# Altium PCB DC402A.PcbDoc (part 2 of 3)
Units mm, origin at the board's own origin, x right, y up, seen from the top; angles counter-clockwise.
Board outline 93 x 73 mm, 4 copper layers (Top Layer, Int1 (GND), Int2 (PWR), Bottom Layer), stack 1.369 mm thick; 244 components, 141 nets, 575 pads, 306 vias.
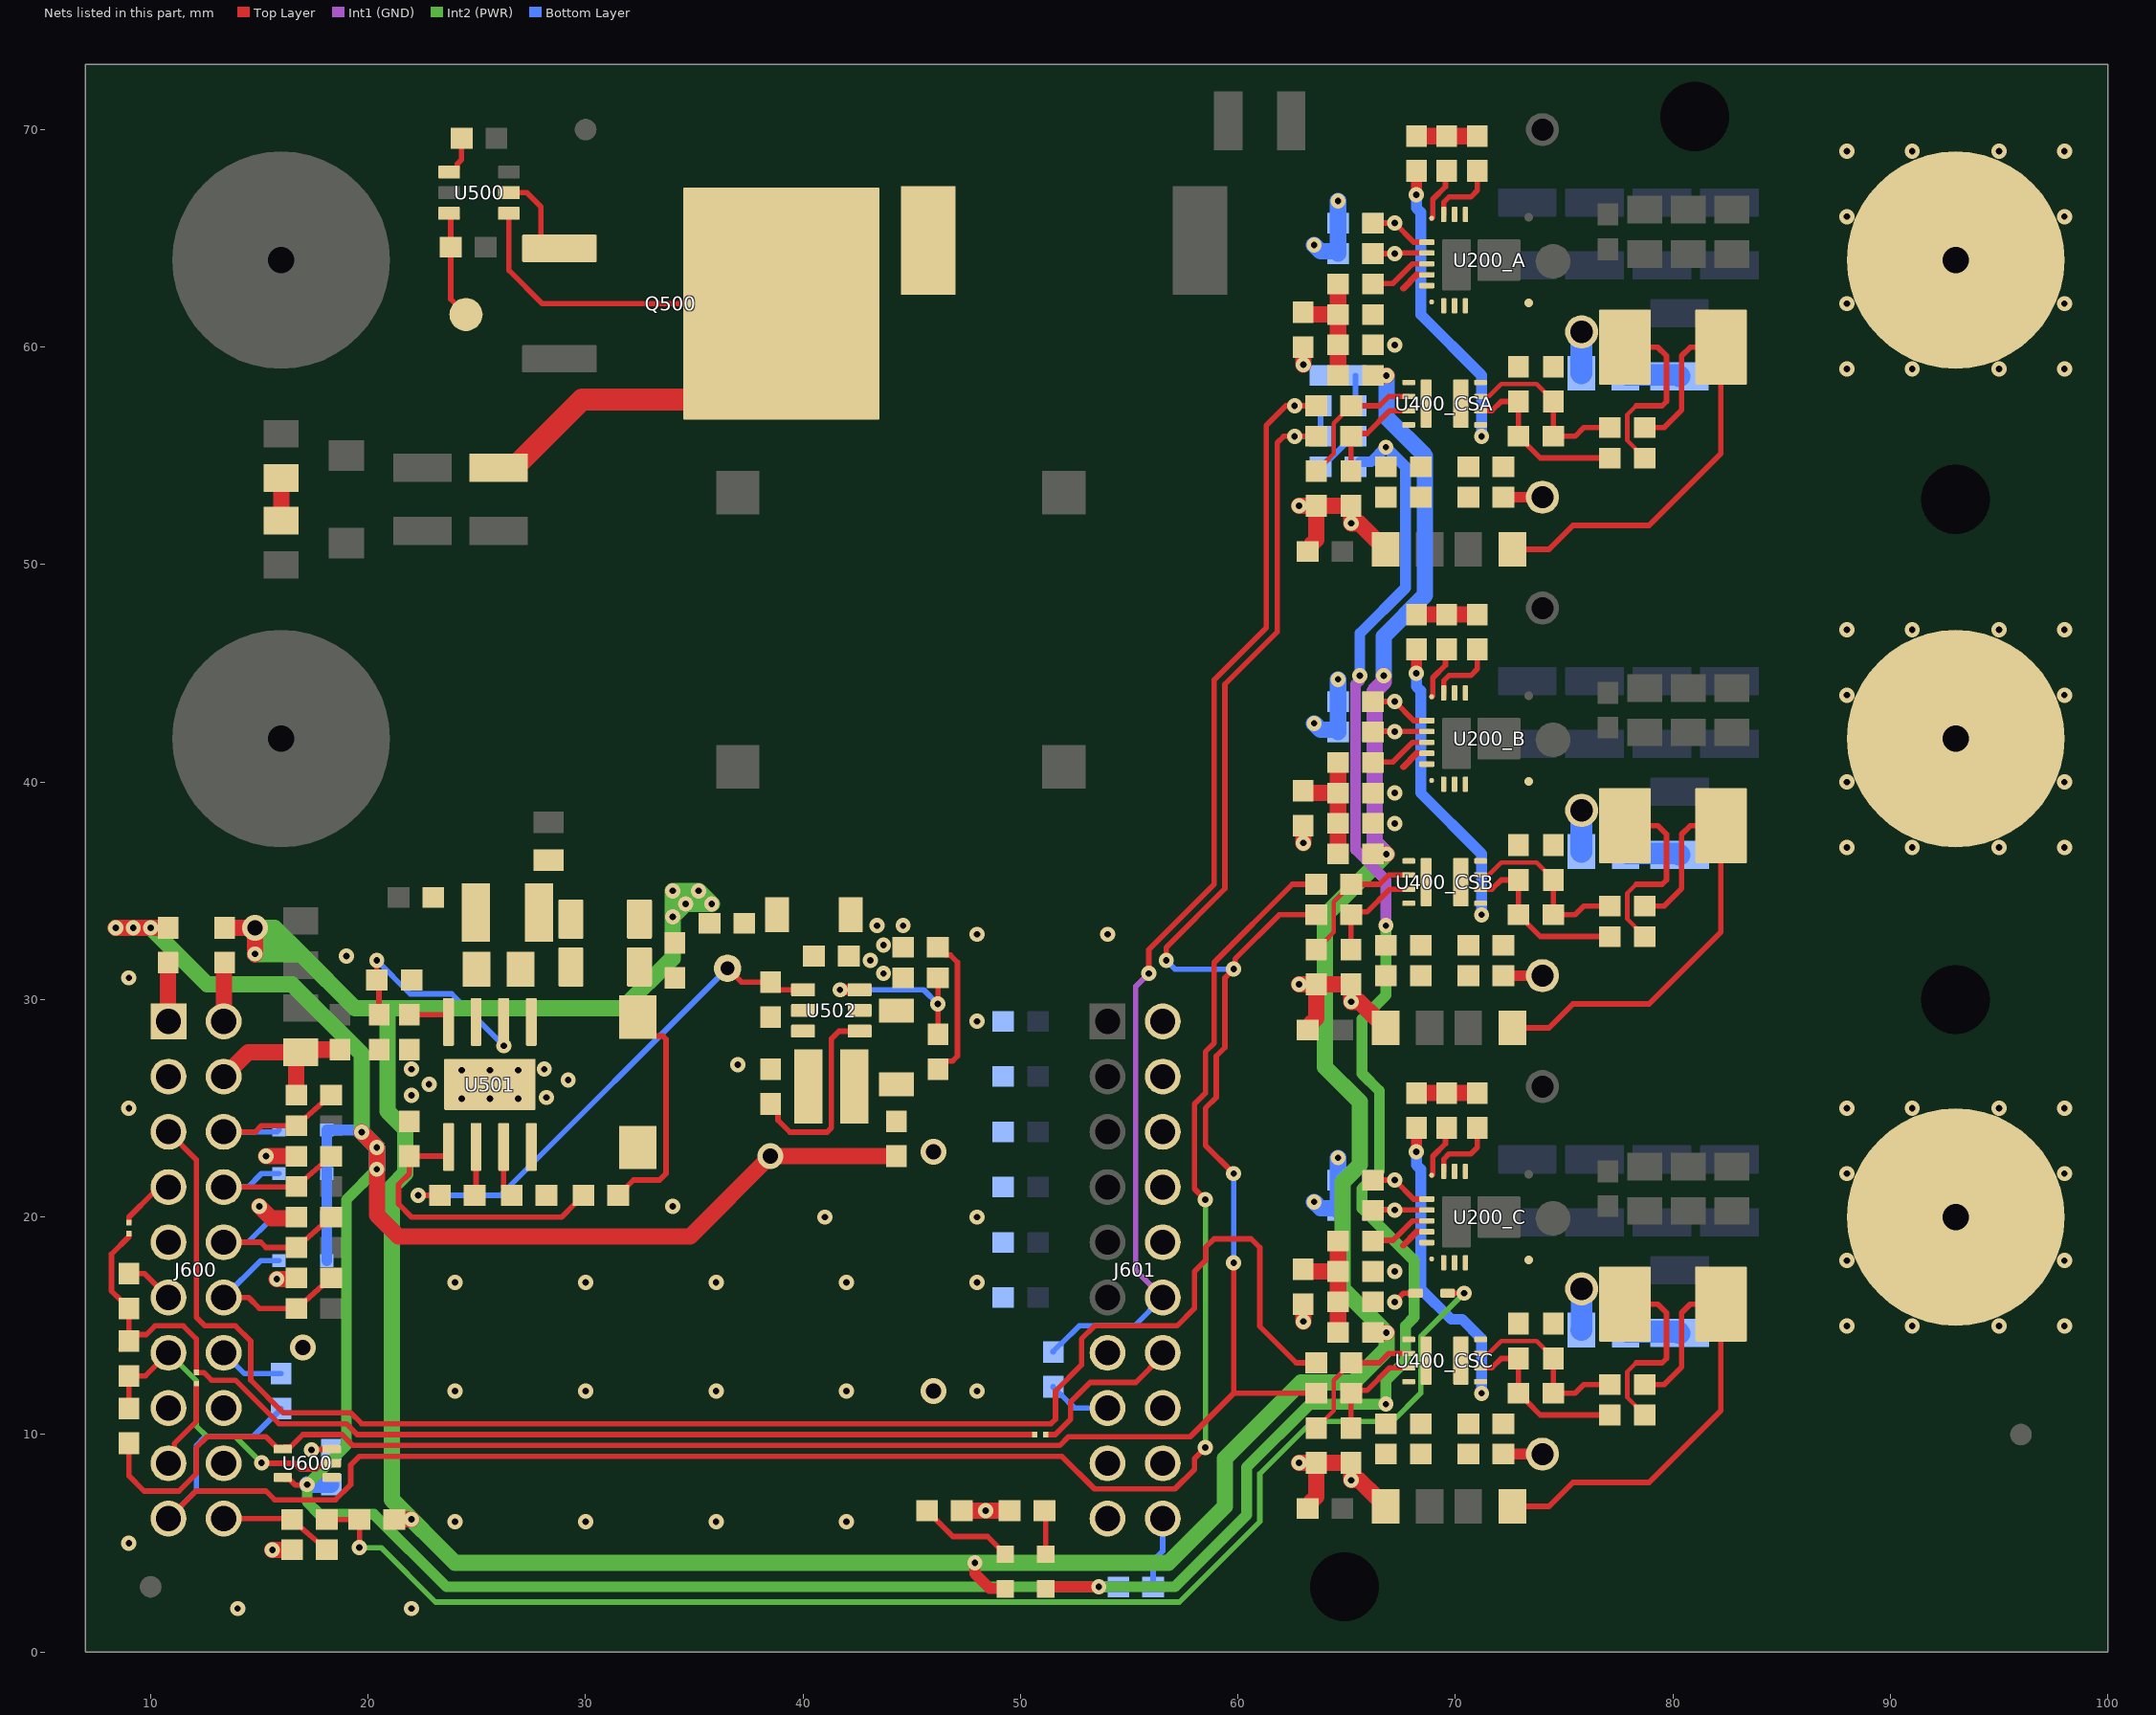
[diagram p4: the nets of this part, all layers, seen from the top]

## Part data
C1 C2: library part CMP-0007197-4, "CAP, CERM, 220 pF, 50 V, +/- 5%, C0G/NP0, 0603", Cap_Case=0603, Manufacturer=MuRata, Supplier Part Number 1=490-1435-1-ND, TempCo=C0G/NP0, Tolerance_%=5%, Value1=Unknown, Value2=50V, ValueDisplayed=220pF
C200_A C200_B C200_C: library part CMP-0007238-4, "CAP, CERM, 1000 pF, 100 V, +/- 5%, C0G/NP0, 0603", Cap_Case=0603, Manufacturer=MuRata, Supplier Part Number 1=490-3281-1-ND, TempCo=C0G/NP0, Tolerance_%=5%, Value1=Unknown, Value2=100V, ValueDisplayed=1000pF
C201_A C201_B C201_C C202_A C202_B C202_C C203_A C203_B C203_C C500 C507 C510: library part CMP-0008249-2, "CAP, CERM, 0.22 uF, 100 V, +/- 10%, X7R, 0805", Cap_Case=0805, Manufacturer=MuRata, Supplier Part Number 1=GRM21AR72A224KAC5-ND, TempCo=X7R, Tolerance_%=10%, Value1=Unknown, Value2=100V, ValueDisplayed=0.22uF
C204_A C204_B C204_C C210_A C210_B C210_C C401_CSA C401_CSB C401_CSC C405_CSA C405_CSB C405_CSC C508 C513 C514 C515 C605: library part CMP-0006837-4, "CAP, CERM, 0.1 uF, 50 V, +/- 10%, X7R, 0603", Cap_Case=0603, Manufacturer="Wurth Elektronik", TempCo=X7R, Tolerance_%=10%, Value1=Unknown, Value2=50V, ValueDisplayed=0.1uF
C205_A C205_B C205_C C206_A C206_B C206_C C207_A C207_B C207_C C208_A C208_B C208_C C503 C504 C509: library part CMP-0009150-2, "CAP, CERM, 4.7 uF, 100 V, +/- 10%, X7S, AEC-Q200 Grade 1, 1210", Cap_Case=1210_220, Manufacturer=TDK, Supplier Part Number 1=445-7005-1-ND, TempCo=X7S, Tolerance_%=10%, Value1="0.004236 ohm", Value2=100V, ValueDisplayed=4.7uF
C209_A C209_B C209_C: library part CMP-0007091-1, "CAP, CERM, 2.2 uF, 10 V, +/- 10%, X5R, AEC-Q200 Grade 3, 0603", Cap_Case=0603, Manufacturer=TDK, Supplier Part Number 1=445-12444-1-ND, TempCo=X5R, Tolerance_%=10%, Value1=Unknown, Value2=10V, ValueDisplayed=2.2uF
C211_A C211_B C211_C: library part CMP-0008113-2, "CAP, CERM, 270 pF, 100 V, +/- 5%, C0G/NP0, 0805", Cap_Case=0805, Manufacturer=MuRata, Supplier Part Number 1=490-1609-1-ND, TempCo=C0G/NP0, Tolerance_%=5%, Value1=Unknown, Value2=100V, ValueDisplayed=270pF
C212_A C212_B C212_C C213_A C213_B C213_C C406_CSA C406_CSB C406_CSC C407_CSA C407_CSB C407_CSC: library part CMP-0006821-4, "CAP, CERM, 15 pF, 50 V, +/- 5%, C0G/NP0, 0603", Cap_Case=0603, Manufacturer="Wurth Elektronik", Supplier Part Number 1=732-7794-1-ND, TempCo=C0G/NP0, Tolerance_%=5%, Value1=Unknown, Value2=50V, ValueDisplayed=15pF
C214_A C214_B C214_C: library part CMP-0007295-4, "CAP, CERM, 10 uF, 10 V, +/- 20%, X6S, 0603", Cap_Case=0603, Manufacturer=MuRata, Supplier Part Number 1=490-7197-1-ND, TempCo=X6S, Tolerance_%=20%, Value1=Unknown, Value2=10V, ValueDisplayed=10uF
C400_CSA C400_CSB C400_CSC C505: library part CMP-0007392-5, "CAP, CERM, 0.033 uF, 16 V, +/- 10%, X7R, 0603", Cap_Case=0603, Manufacturer=MuRata, Supplier Part Number 1=490-1528-1-ND, TempCo=X7R, Tolerance_%=10%, Value1=Unknown, Value2=16V, ValueDisplayed=0.033uF
C402_CSA C402_CSB C402_CSC C404_CSA C404_CSB C404_CSC: library part CMP-0007498-4, "CAP, CERM, 4.7 uF, 10 V, +/- 20%, X7R, 0603", Cap_Case=0603, Manufacturer=MuRata, TempCo=X7R, Tolerance_%=20%, Value1=Unknown, Value2=10V, ValueDisplayed=4.7uF
C403_CSA C403_CSB C403_CSC: library part CMP-0007174-4, "CAP, CERM, 0.01 uF, 50 V, +/- 5%, C0G/NP0, 0603", Cap_Case=0603, Manufacturer=MuRata, Supplier Part Number 1=490-9666-1-ND, TempCo=C0G/NP0, Tolerance_%=5%, Value1=Unknown, Value2=50V, ValueDisplayed=0.01uF
C408_CSA C408_CSB C408_CSC C409_CSA C409_CSB C409_CSC: library part CMP-0007221-4, "CAP, CERM, 470 pF, 50 V, +/- 5%, C0G/NP0, 0603", Cap_Case=0603, Manufacturer=MuRata, Supplier Part Number 1=490-1443-1-ND, TempCo=C0G/NP0, Tolerance_%=5%, Value1=Unknown, Value2=50V, ValueDisplayed=470pF
C501 C502: library part CMP-0011411-2, "CAP, AL, 150 uF, 80 V, +/- 20%, 0.2 ohm, AEC-Q200 Grade 1, SMD", Cap_Case=12.5x13.5mm, Manufacturer=Nichicon, Supplier Part Number 1=493-13956-1-ND, Tolerance_%=20%, Value1="0.2 ohm", Value2=80V, ValueDisplayed=150uF
C506: library part CMP-0007343-5, "CAP, CERM, 1 uF, 25 V, +/- 10%, X5R, 0603", Cap_Case=0603, Manufacturer=MuRata, Supplier Part Number 1=490-3897-1-ND, TempCo=X5R, Tolerance_%=10%, Value1=Unknown, Value2=25V, ValueDisplayed=1uF
C511 C512: library part CMP-0123891-1, "Chip Multilayer Ceramic Capacitors for General Purpose, 1206, 22uF, X7R, 15%, 20%, 16V", Manufacturer=Murata, Operating Temperature Range="-55°C to +125°C", TempCo=15%, Temperature Characteristic=X7R, Tolerance_%=20%, ValueDisplayed=22uF
C516 C517: library part CMP-0081454-1, "CAP, CERM, 10 µF, 50 V,+/- 20%, X5R, 1206", Cap_Case=1206, Manufacturer="Wurth Elektronik", TempCo=X5R, Tolerance_%=20%, Value2=50V, ValueDisplayed=10µF
C600 C601 C602 C603 C604: library part CMP-0007198-2, "CAP, CERM, 2200 pF, 50 V, +/- 5%, C0G/NP0, 0603", Cap_Case=0603, Manufacturer=MuRata, Supplier Part Number 1=490-1459-1-ND, TempCo=C0G/NP0, Tolerance_%=5%, Value1=Unknown, Value2=50V, ValueDisplayed=2200pF
D500: library part CMP-0085026-1, "Diode, TVS, Bi, 64 V, 103 Vc, 400 W, 3.9 A, SMA (non-polarized)", Manufacturer=Littelfuse, Value1=103V
D600 D601 D602 D603: library part CMP-0079597-2, "Diode, Switching, 75 V, 0.15 A, AEC-Q101, SOD-323", Manufacturer="Diodes Inc.", Value1=0.15A, Value2=1.25V
D604: library part CMP-0002905-1, "LED, Green, SMD", Color=Green, Manufacturer="Wurth Elektronik", Supplier Part Number 1=732-4971-1-ND, Value1=W, Value2=3.2V
D605: library part CMP-0002947-3, "LED, Red, SMD", Color=Red, Manufacturer="Wurth Elektronik", Power_TotalModule=72mW, Value1=0.072W, Value2=2V
FID300 FID301 FID302: library part CMP-0077181-1, "Fiducial mark.  There is nothing to buy or mount.", Manufacturer=N/A
J600 J601: "Connector, Receptacle, 100mil, 10x2, Gold plated, TH", Manufacturer=Samtec, PartNumber=SSW-110-23-F-D
L500: library part CMP-0098596-1, "WE-HCM SMT High Current Flat Wire Inductor, size 1390, 0.2uH, 47.5A, 0.165mOhm", Case/Size Code=1390, DC Resistance=0.165mOhm, Inductance=0.47uH, Manufacturer="Wurth Elektronik", Operating Temperature Max=125°C, Operating Temperature Min=-40°C, Rated Current=47.5A, Rated Inductance=0.2uH, Saturation Current=46.8A, Self Resonant Frequency=22MHz
L501: library part CMP-0064659-1, "Inductor, Shielded Drum Core, Ferrite, 33 uH, 1.15 A, 0.153 ohm, SMD", Manufacturer="Wurth Elektronik", Supplier Part Number 1=732-1181-1-ND, Value1="0.153 ohm", Value2=1.15A, ValueDisplayed=33uH
L502: library part CMP-0101711-1, "WE-MAIA SMT Power Inductor, size 3015, 4.7uH, 1.5A, 162mOhm", Case/Size Code=3015, DC Resistance=141mOhm, DC Resistance Max=162mOhm, Inductance=4.7uH, Manufacturer="Wurth Elektronik", Operating Temperature Max=125°C, Operating Temperature Min=-40°C, Rated Current=1.5A, Saturation Current=2.8A, Self Resonant Frequency=30MHz
LBL300: library part CMP-0003625-1, "Thermal Transfer Printable Labels, 0.650\" W x 0.200\" H - 10,000 per roll", Manufacturer=Brady, Supplier Part Number 1=97C5133
Logo300: library part CMP-0074844-1
Logo301: library part CMP-0074838-1, "Texas Instrument Corporate Signature"
Logo302: library part CMP-0074847-1, "FCC_disclaimer"
Logo303: library part CMP-0074769-1
MH1 MH2 MH3 MH4: library part CMP-0078424-2, "PCB Mounting Hole, No Pad", Manufacturer=Any, PartNumber=N/A
MP1 MP2 MP3 MP4 MP5: library part CMP-03913-88496621-1, "7466105 WP-SMBU REDCUBE Bush, SMT_closed_pin", Current Rating=70A, Max Operating Temperature=150°C, Min Operating Temperature=-55°C
NT600 NT601 NT602: library part CMP-0078142-2, "Single point connection between nets.", Manufacturer=N/A
Q500: library part CMP-0001032-4, "MOSFET, N-CH, 100 V, 180 A, DDPAK", Alternate Manufacturer=None, Manufacturer=STMicroelectronics, Supplier Part Number 1=497-13585-1-ND, Value2="180 nC"
R1: library part CMP-0020833-2, "RES, 0, 1%, 0.5 W, 0805", Manufacturer=Keystone, Power_W=500mW, Supplier Part Number 1=36-5106CT-ND, TempCo=ppm/C, Tolerance_%=1%, Value2=0.5W, Value_Code=0
R2 R3 R4: library part CMP-0042666-1, "Res Metal Strip 2512 0.001 Ohm 1% 3W ±50ppm/C Pad SMD Automotive T/R", Manufacturer="TT Electronics", Mouser Part Number=66-ULRG3R001FLFSLT, Operating Temperature Range=to, Power_W=3W, TempCo=50ppm/°C, Tolerance_%=1%
R5 R6: library part CMP-0022736-4, "RES, 100, 1%, 0.1 W, 0603", Manufacturer=Yageo, Power_W=100mW, Supplier Part Number 1=311-100HRCT-ND, TempCo="100 ppm/C", Tolerance_%=1%, Value2=0.1W, Value_Code=100R, ValueDisplayed=100
R200_A R200_B R200_C R202_A R202_B R202_C: library part CMP-0025885-5, "RES, 0, 5%, 0.1 W, 0603", Manufacturer=Yageo, Power_W=100mW, Supplier Part Number 1=311-0.0GRCT-ND, TempCo="200 ppm/C", Tolerance_%=5%, Value2=0.1W, Value_Code=0000, ValueDisplayed=0
R201_A R201_B R201_C R203_A R203_B R203_C: library part CMP-0023010-4, "RES, 2.74, 1%, 0.1 W, 0603", Manufacturer=Yageo, Power_W=100mW, Supplier Part Number 1=311-2.74HRCT-ND, TempCo="200 ppm/C", Tolerance_%=1%, Value2=0.1W, Value_Code=2R74, ValueDisplayed=2.74
R204_A R204_B R204_C R205_A R205_B R205_C R402_CSA R402_CSB R402_CSC R403_CSA R403_CSB R403_CSC R404_CSA R404_CSB R404_CSC R405_CSA R405_CSB R405_CSC R605 R606 R607 R608 R615: library part CMP-0022751-4, "RES, 10.0, 1%, 0.1 W, 0603", Manufacturer=Yageo, Power_W=100mW, Supplier Part Number 1=311-10.0HRCT-ND, TempCo="100 ppm/C", Tolerance_%=1%, Value2=0.1W, Value_Code=10R0, ValueDisplayed=10.0
R206_A R206_B R206_C: library part CMP-0083057-1, "RES, 2.70, 1%, 0.5 W, 1210", Manufacturer=Yageo, Power_W=500mW, TempCo="200 ppm/C", Tolerance_%=1%, Value2=0.5W, Value_Code=2R70, ValueDisplayed=2.70
R400_CSA R400_CSB R400_CSC R500: library part CMP-0021521-3, "RES, 100 k, 1%, 0.125 W, AEC-Q200 Grade 0, 0805", Manufacturer=Panasonic, Power_W=125mW, Supplier Part Number 1=P100KCCT-ND, TempCo="100 ppm/C", Tolerance_%=1%, Value2=0.125W, Value_Code=100k
R401_CSA R401_CSB R401_CSC R502: library part CMP-0021711-3, "RES, 4.22 k, 1%, 0.125 W, AEC-Q200 Grade 0, 0805", Manufacturer=Panasonic, Power_W=125mW, Supplier Part Number 1=P4.22KCCT-ND, TempCo="100 ppm/C", Tolerance_%=1%, Value2=0.125W, Value_Code=4k22, ValueDisplayed=4.22k
R501: library part CMP-0083501-1, "RES, 22 k, 5%, 0.5 W, 1210", Manufacturer=Yageo, Power_W=500mW, TempCo="100 ppm/C", Tolerance_%=5%, Value2=0.5W, Value_Code=22k0, ValueDisplayed=22k
R503 R506 R509 R515: library part CMP-0022735-5, "RES, 100 k, 1%, 0.1 W, 0603", Manufacturer=Yageo, Power_W=100mW, Supplier Part Number 1=311-100KHRCT-ND, TempCo="100 ppm/C", Tolerance_%=1%, Value2=0.1W, Value_Code=100k
R504 R505 R508 R512 R514 R603 R604 R613 R614 R617 R618 R621: library part CMP-0086358-1, "RES, 0, 0%, 0.25 W, AEC-Q200 Grade 0, 0603", Manufacturer=Rohm, Power_W=250mW, Tolerance_%=0%, Value2=0.25W, Value_Code=0000, ValueDisplayed=0
R507: library part CMP-0023098-5, "RES, 40.2 k, 1%, 0.1 W, 0603", Manufacturer=Yageo, Power_W=100mW, Supplier Part Number 1=311-40.2KHRCT-ND, TempCo="100 ppm/C", Tolerance_%=1%, Value2=0.1W, Value_Code=40k2, ValueDisplayed=40.2k
R510: library part CMP-0023228-5, "RES, 64.9 k, 1%, 0.1 W, 0603", Manufacturer=Yageo, Power_W=100mW, Supplier Part Number 1=311-64.9KHRCT-ND, TempCo="100 ppm/C", Tolerance_%=1%, Value2=0.1W, Value_Code=64k9, ValueDisplayed=64.9k
R511 R600 R601 R602 R609 R610 R611 R612 R616: library part CMP-0022746-5, "RES, 10.0 k, 1%, 0.1 W, 0603", Manufacturer=Yageo, Power_W=100mW, Supplier Part Number 1=311-10.0KHRCT-ND, TempCo="100 ppm/C", Tolerance_%=1%, Value2=0.1W, Value_Code=10k0, ValueDisplayed=10.0k
R513: library part CMP-0023167-5, "RES, 51.0 k, 1%, 0.1 W, 0603", Manufacturer=Yageo, Power_W=100mW, Supplier Part Number 1=311-51.0KHRCT-ND, TempCo="100 ppm/C", Tolerance_%=1%, Value2=0.1W, Value_Code=51k0, ValueDisplayed=51.0k
R516: library part CMP-0022923-5, "RES, 22.1 k, 1%, 0.1 W, 0603", Manufacturer=Yageo, Power_W=100mW, Supplier Part Number 1=311-22.1KHRCT-ND, TempCo="100 ppm/C", Tolerance_%=1%, Value2=0.1W, Value_Code=22k1, ValueDisplayed=22.1k
R619: library part CMP-0023153-5, "RES, 4.70 k, 1%, 0.1 W, 0603", Manufacturer=Yageo, Power_W=100mW, Supplier Part Number 1=311-4.70KHRCT-ND, TempCo="100 ppm/C", Tolerance_%=1%, Value2=0.1W, Value_Code=4k70, ValueDisplayed=4.70k
R620: library part CMP-0022887-5, "RES, 1.60 k, 1%, 0.1 W, 0603", Manufacturer=Yageo, Power_W=100mW, Supplier Part Number 1=311-1.60KHRCT-ND, TempCo="100 ppm/C", Tolerance_%=1%, Value2=0.1W, Value_Code=1k60, ValueDisplayed=1.60k
RT600: library part CMP-0091865-2, "±1% tolerance 10kΩ linear thermistor available in 0402 and 0603 package options 2-SOT-5X3 -40 to 125", Digikey Part Number=296-TMP6131DYATCT-ND, Manufacturer="Texas Instruments", Max Current=400uA, Mouser Part Number=595-TMP6131DYAT, Operating Temperature Range="-40°C to +125°C", TempCo=6400ppm/°C, Tolerance_%=1%
TP200_A TP200_B TP200_C TP201_A TP201_B TP201_C TP400_CSA TP400_CSB TP400_CSC TP500 TP501: library part CMP-0078143-4, "TEST POINT.  No entry in BOM.", Manufacturer=N/A
U200_A U200_B U200_C: library part CMP-0121493-2, "100-V, 53-A GaN Half-Bridge Power Stage", Manufacturer="Texas Instruments", Max Supply Voltage=5.25V, Min Supply Voltage=4.75V, Nominal Supply Current=12mA, Operating Temperature Range="-40°C to +150°C"
U400_CSA U400_CSB U400_CSC: library part CMP-0049066-2, "±50 mV Input Functionally Isolated Delta-Sigma Modulator for Current Sensing, VSON8", Manufacturer="Texas Instruments", Operating Temperature Range="-40°C to +125°C"
U500: library part CMP-0013281-4, "Low Iq Always ON Smart Diode Controller, DBV0006A (SOT-23-6)", Alternate Manufacturer="Texas Instruments", Alternate PartNumber=LM74700QDBVTQ1
U501: library part CMP-0096892-1, "4.2-V to 80-V, 1-A Synchronous Buck Converter with 40-µA IQ", Manufacturer="Texas Instruments", Max Supply Voltage=80V, Min Supply Voltage=4.2V, Mouser Part Number=595-LMR38010FDDAR, Nominal Supply Current=40uA, Operating Temperature Range="-40°C to +150°C", Output Voltage=1-75V, Switching Frequency=200-2200kHz
U502: library part CMP-0090796-2, "SIMPLE SWITCHER 4-V to 36-V, 1-A Buck Converter in SOT-23-6 package", Manufacturer="Texas Instruments", Max Supply Voltage=36V, Min Supply Voltage=4V, Nominal Supply Current=80-90uA, Operating Temperature Range="-40°C to +150°C", Output Voltage=1-28V, Switching Frequency=2.1MHz
U600: library part CMP-0051710-3, "Automotive Catalog Single Schmitt-Trigger Buffer, DCK0005A, LARGE T&R", F @ Nom Voltage(Max)(Mhz)=150, Generic Part Number=SN74LVC1G17-Q1, ICC @ Nom Voltage(Max)(mA)=0.02, Manufacturer="Texas Instruments", Operating Temperature Range(C)="-40 to 125", Rating=Automotive, tpd @ Nom Voltage(Max)(ns)=14,9,8,7, Voltage(Nom)(V)=1.8,2.5,3.3,5
ZZ300: library part CMP-0003616-3
ZZ301: library part CMP-0077236-1
ZZ302: library part CMP-0077237-1
ZZ303: library part CMP-0077238-1

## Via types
v1: diameter 0.7, hole 0.3, Top Layer to Bottom Layer, tented both sides, 277 vias
v2: diameter 1.2, hole 0.7, Top Layer to Bottom Layer, 10 vias
v3: diameter 0.5, hole 0.2, Top Layer to Bottom Layer, tented both sides, 9 vias
v4: diameter 0.7, hole 0.3, Top Layer to Bottom Layer, 9 vias
v5: diameter 1.2, hole 0.7, Top Layer to Bottom Layer, tented bottom, 1 vias

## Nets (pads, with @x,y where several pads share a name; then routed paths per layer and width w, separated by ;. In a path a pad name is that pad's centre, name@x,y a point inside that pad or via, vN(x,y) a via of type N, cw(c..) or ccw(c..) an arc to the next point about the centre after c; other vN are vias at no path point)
AVDD_CSA: C404_CSA.1 C405_CSA.1 R202_A.1 TP400_CSA.1 U400_CSA.1 | length 15.2
  Top Layer w0.5: v1(68.2,67) R202_A.1@68.2,68.1 ; C405_CSA.1@72.2,53.1 TP400_CSA.1@74,53.1
  Bottom Layer w0.5: v1(68.2,67) 68.2,66.4 68.4,66.2 68.4,61.5 71.2,58.7 v1(71.2,55.9)
AVDD_CSB: C404_CSB.1 C405_CSB.1 R202_B.1 TP400_CSB.1 U400_CSB.1 | length 15.2
  Top Layer w0.5: v1(68.2,45) R202_B.1@68.2,46.1 ; C405_CSB.1@72.2,31.1 TP400_CSB.1@74,31.1
  Bottom Layer w0.5: v1(68.2,45) 68.2,44.4 68.4,44.2 68.4,39.5 71.2,36.7 v1(71.2,33.9)
AVDD_CSC: C404_CSC.1 C405_CSC.1 R202_C.1 TP400_CSC.1 U400_CSC.1 | length 15.5
  Top Layer w0.5: v1(68.2,23) R202_C.1@68.2,24.1 ; C405_CSC.1@72.2,9.1 TP400_CSC.1@74,9.1
  Bottom Layer w0.5: v1(68.2,23) 68.2,22.4 68.4,22.2 68.4,16.7 69.8,15.3 70.306,15.3 71.2,14.406 v1(71.2,11.9)
DCDC_EN: R508.1 R515.1 TP501.1 U502.4 | length 23.6
  Top Layer w0.25: v1(22.3,21) R508.1@23.3,21 ; TP501.1@36.527,31.441 37.168,30.8 R515.1@38.5,30.8 38.5,30.45 U502.4@40,30.45
  Bottom Layer w0.25: v1(22.3,21) 26.086,21 TP501.1@36.527,31.441
DGND: C204_A.2 C204_B.2 C204_C.2 C209_A.2 C209_B.2 C209_C.2 C212_A.2 C212_B.2 C212_C.2 C213_A.2 C213_B.2 C213_C.2 C214_A.2 C214_B.2 C214_C.2 C400_CSA.2 C400_CSB.2 C400_CSC.2 C401_CSA.2 C401_CSB.2 C401_CSC.2 C402_CSA.2 C402_CSB.2 C402_CSC.2 C406_CSA.2 C406_CSB.2 C406_CSC.2 C407_CSA.2 C407_CSB.2 C407_CSC.2 C505.2 C509.2 C510.2 C511.1 C512.1 C514.2 C515.2 C516.2 C517.2 C600.2 C601.2 C602.2 C603.2 C604.2 C605.2 J600.4 J601.2 R1.2 R6.2 R401_CSA.1 R401_CSB.1 R401_CSC.1 R502.1 R509.2 R510.1 R511.1 R516.1 R600.2 R601.2 R602.2 R609.1 R610.1 R611.1 R619.1 R620.1 RT600.1 U200_A.15 U200_B.15 U200_C.15 U400_CSA.5 U400_CSB.5 U400_CSC.5 U501.1 U501.9 U502.2 U600.3 | length 57.2
  Top Layer w0.25: v1(17.4,9.3) 17.415,9.315 18.31,9.315 U600.3@18.325,9.33 ; v1(67.2,16.1) 67.6,16.5 RT600.1@68.16,16.5 ; 68.225,19.325 U200_C.15@68.682,19.325 ; 68.225,41.325 U200_B.15@68.682,41.325 ; 68.225,63.325 U200_A.15@68.682,63.325
  Top Layer w0.3: 67.6,18.7 68.225,19.325 ; 67.6,40.7 68.225,41.325 ; 67.6,62.7 68.225,63.325
  Top Layer w0.75: J600.4@13.36,26.46 14.484,27.584 R502.1@16.7,27.584 ; v1(15,20.5) 15.55,19.95 C601.2@16.65,19.95 ; v1(15.3,22.8) 16.6,22.8 C602.2@16.65,22.75 ; v1(15.6,4.7) C604.2@16.5,4.7 ; v1(15.8,17.15) 16.65,17.15 C600.2@16.7,17.2 ; C603.2@16.7,25.6 R502.1@16.7,27.584 ; R502.1@16.9,27.584 R502.1@16.7,27.584 ; R502.1@16.9,27.7 C505.2@18.7,27.7 ; R620.1@47.3,6.5 v1(48.4,6.5) R619.1@49.5,6.5 ; v1(62.8,8.7) C406_CSC.2@65.2,8.7 v1(65.2,7.9) 65.584,7.9 R401_CSC.1@66.359,7.125 ; v1(62.8,30.7) C407_CSB.2@63.6,30.7 C406_CSB.2@65.2,30.7 v1(65.2,29.9) 65.584,29.9 R401_CSB.1@66.359,29.125 ; v1(62.8,52.7) C407_CSA.2@63.6,52.7 C406_CSA.2@65.2,52.7 v1(65.2,51.9) 65.584,51.9 66.359,51.125 66.524,51.125 66.784,50.865 R401_CSA.1@66.784,50.7 ; v1(63,15.2) C214_C.2@63,16 ; v1(63,37.2) C214_B.2@63,38 ; v4(63,59.2) C214_A.2@63,60 ; C400_CSC.2@63.2,6.6 63.225,6.6 63.325,6.7 63.325,6.864 63.6,7.139 C407_CSC.2@63.6,8.675 ; C400_CSB.2@63.2,28.6 63.225,28.6 63.325,28.7 63.325,28.864 63.6,29.139 C407_CSB.2@63.6,30.675 ; C400_CSA.2@63.2,50.6 63.225,50.6 63.325,50.7 63.325,50.864 63.6,51.139 C407_CSA.2@63.6,52.675 ; R401_CSC.1@66.524,7.125 66.784,6.865 R401_CSC.1@66.784,6.7 ; R401_CSB.1@66.524,29.125 66.784,28.865 R401_CSB.1@66.784,28.7
  Bottom Layer w0.75: v1(63.5,20.7) 63.8,20.4 64.5,20.4 C212_C.2@64.6,20.3 C213_C.2@64.6,21.7 v1(64.6,22.725) ; v1(63.5,42.7) 63.8,42.4 64.5,42.4 C212_B.2@64.6,42.3 C213_B.2@64.6,43.7 v1(64.6,44.725) ; v1(63.5,64.7) 63.8,64.4 64.5,64.4 C212_A.2@64.6,64.3 C213_A.2@64.6,65.7 v1(64.6,66.725)
  other v1: 14,2 22,2 9,5 24,6 30,6 36,6 42,6 24,12 30,12 36,12 42,12 48,12 24,17 30,17 36,17 42,17 48,17 67.2,17.5 41,20 48,20 34,20.5 9,25 24.3,25.45 25.6,25.45 26.9,25.45 28.2,25.5 22,25.6 22.8,26.1 29.2,26.3 24.3,26.75 25.6,26.75 26.9,26.75 22,26.8 28.1,26.8 37,27 48,29 9,31 43.7,31.2 43.1,31.8 19,32 43.7,32.5 48,33 54,33 43.4,33.4 44.6,33.4 67.2,38.1 67.2,39.5 67.2,60.1
  other v2: 46,12 17,14 46,23
INN_CSA: MP3.1 R2.2 R400_CSA.1 R402_CSA.2 | length 22.8
  Top Layer w0.25: R400_CSA.1@72.616,50.7 74.3,50.7 75.4,51.8 78.9,51.8 82.201,55.101 R2.2@82.201,59.991 ; R402_CSA.2@78.7,56.3 79.6,56.3 80.4,57.1 80.4,59.6 80.791,59.991 R2.2@82.201,59.991 ; R2.2@82.21,60 R2.2@82.201,59.991
  other v1: 88,59 91,59 95,59 98,59 88,62 98,62 88,66 98,66 88,69 91,69 95,69 98,69
INN_CSB: MP4.1 R3.2 R400_CSB.1 R402_CSB.2 | length 22.8
  Top Layer w0.25: R400_CSB.1@72.616,28.7 74.3,28.7 75.4,29.8 78.9,29.8 82.201,33.101 R3.2@82.201,37.991 ; R402_CSB.2@78.7,34.3 79.6,34.3 80.4,35.1 80.4,37.6 80.791,37.991 R3.2@82.201,37.991 ; R3.2@82.21,38 R3.2@82.201,37.991
  other v1: 88,37 91,37 95,37 98,37 88,40 98,40 88,44 98,44 88,47 91,47 95,47 98,47
INN_CSC: MP5.1 R4.2 R400_CSC.1 R402_CSC.2 | length 22.8
  Top Layer w0.25: R400_CSC.1@72.616,6.7 74.3,6.7 75.4,7.8 78.9,7.8 82.201,11.101 R4.2@82.201,15.991 ; R402_CSC.2@78.7,12.3 79.6,12.3 80.4,13.1 80.4,15.6 80.791,15.991 R4.2@82.201,15.991 ; R4.2@82.21,16 R4.2@82.201,15.991
  other v1: 88,15 91,15 95,15 98,15 88,18 98,18 88,22 98,22 88,25 91,25 95,25 98,25
INP_CSA: C211_A.1 C404_CSA.2 C405_CSA.2 C408_CSA.2 C409_CSA.2 R2.1 R403_CSA.2 TP200_A.1 U200_A.5 U400_CSA.4 | length 10.5
  Top Layer w0.2: 78.3,57.3 77.9,56.9 77.9,55.7 78.3,55.3 78.3,55.275 78.675,54.9 R403_CSA.2@78.7,54.9
  Top Layer w0.25: R2.1@77.79,60 79.3,60 79.7,59.6 79.7,57.5 79.5,57.3 78.3,57.3
  Bottom Layer w1: C211_A.1@75.784,58.8 75.792,58.808 75.792,60.692 TP200_A.1@75.8,60.7
INP_CSB: C211_B.1 C404_CSB.2 C405_CSB.2 C408_CSB.2 C409_CSB.2 R3.1 R403_CSB.2 TP200_B.1 U200_B.5 U400_CSB.4 | length 10.5
  Top Layer w0.2: 78.3,35.3 77.9,34.9 77.9,33.7 78.3,33.3 78.3,33.275 78.675,32.9 R403_CSB.2@78.7,32.9
  Top Layer w0.25: R3.1@77.79,38 79.3,38 79.7,37.6 79.7,35.5 79.5,35.3 78.3,35.3
  Bottom Layer w1: C211_B.1@75.784,36.8 C211_B.1@75.792,36.808 75.792,38.692 TP200_B.1@75.8,38.7
INP_CSC: C211_C.1 C404_CSC.2 C405_CSC.2 C408_CSC.2 C409_CSC.2 R4.1 R403_CSC.2 TP200_C.1 U200_C.5 U400_CSC.4 | length 10.5
  Top Layer w0.2: 78.3,13.3 77.9,12.9 77.9,11.7 78.3,11.3 78.3,11.275 78.675,10.9 R403_CSC.2@78.7,10.9
  Top Layer w0.25: R4.1@77.79,16 79.3,16 79.7,15.6 79.7,13.5 79.5,13.3 78.3,13.3
  Bottom Layer w1: C211_C.1@75.792,14.808 75.8,14.816 TP200_C.1@75.8,16.7
MOD_C_phA: J601.14 NT602.2 | length 7.5
  Top Layer w0.25: NT602.2@51.154,10 51.6,10 52.3,10.7 52.3,11.5 53.2,12.4 55.3,12.4 56.54,13.64 J601.14@56.54,13.76
MOD_C_phB: J600.17 NT601.2 | length 4.2
  Top Layer w0.25: J600.17@10.82,8.68 11.088,8.948 11.088,9.588 12.1,10.6 NT601.2@12.1,12.346
MOD_C_phC: J600.7 NT600.2 | length 2.6
  Top Layer w0.25: NT600.2@9,19.771 9,19.873 9,20 10.112,21.112 10.552,21.112 J600.7@10.82,21.38
MOD_CLK: C1.1 C2.2 R404_CSA.1 R404_CSB.1 R404_CSC.1 R621.2 U600.4 | length 119.2
  Top Layer w0.25: R621.2@9,9.6 9,8.1 9.7,7.4 11.3,7.4 12.1,8.2 12.1,9.4 12.6,9.9 15.3,9.9 15.85,9.35 16.075,9.35 16.15,9.425 16.425,9.425 17,10 18.8,10 19.3,9.5 51.8,9.5 52.2,9.9 57.8,9.9 59.8,11.9 ; v1(56.7,31.8) 56.7,32.4 59.4,35.1 59.4,44.5 61.8,46.9 61.8,55.6 62.1,55.9 v4(62.6,55.9) R404_CSA.1@63.6,55.9 ; v1(59.8,17.9) 59.8,11.9 ; v1(59.8,22) 58.5,23.3 58.5,25 59,25.5 59,27.4 59.4,27.8 59.4,31 v1(59.8,31.4) 59.863,31.463 59.863,31.863 61.9,33.9 R404_CSB.1@63.6,33.9 ; R404_CSC.1@63.6,11.9 59.8,11.9
  Bottom Layer w0.25: v1(56.7,31.8) 57.1,31.4 v1(59.8,31.4) ; v1(59.8,17.9) v1(59.8,22) ; v4(62.6,55.9) C1.1@63.8,55.9 C2.2@63.8,57.3
MOD_D_phA: J601.12 R405_CSA.1 R614.1 | length 51.9
  Top Layer w0.25: v1(55.9,31.2) 55.9,32.3 58.9,35.3 58.9,44.7 61.3,47.1 61.3,56.4 62.2,57.3 v4(62.6,57.3) R405_CSA.1@63.6,57.3
  Int1 (GND) w0.25: v1(55.9,31.2) 55.3,30.6 55.3,17.54 J601.12@56.54,16.3
  Bottom Layer w0.25: R614.1@51.5,13.8 51.5,13.825 51.85,14.175 51.875,14.175 52.7,15 55.24,15 J601.12@56.54,16.3
MOD_D_phB: J600.19 R405_CSB.1 R613.2 | length 89
  Top Layer w0.25: J600.19@10.82,6.14 12.08,7.4 15.3,7.4 15.7,7 18.5,7 19.2,7.7 19.2,8.6 19.6,9 51.9,9 53.4,7.5 57.1,7.5 58,8.4 58,8.9 v1(58.5,9.4) ; v1(58.5,20.8) 58,21.3 58,25.2 58.5,25.7 58.5,27.6 58.9,28 58.9,31.7 62.5,35.3 R405_CSB.1@63.6,35.3
  Int2 (PWR) w0.25: v1(58.5,9.4) v1(58.5,20.8)
  Bottom Layer w0.25: J600.19@10.82,6.14 12.1,7.42 12.1,9.5 12.5,9.9 14.7,9.9 15.625,10.825 15.65,10.825 16,11.175 R613.2@16,11.2
MOD_D_phC: J600.5 R405_CSC.1 | length 74.4
  Top Layer w0.25: J600.5@10.82,23.92 12.1,22.64 12.1,15.4 12.5,15 13.9,15 14.6,14.3 14.6,12.5 16.1,11 19.2,11 19.7,10.5 51.4,10.5 51.604,10.704 51.604,12.004 52.8,13.2 52.8,14.4 53.4,15 57.2,15 58,15.8 58,17.5 58.5,18 58.5,18.6 58.9,19 60.6,19 61,18.6 61,14.978 62.678,13.3 R405_CSC.1@63.6,13.3
NetC1_2: C1.2 R5.2 | length 2.2
  Bottom Layer w0.25: R5.2@63.8,54.5 64.15,54.85 64.228,54.85 64.928,55.55 65.05,55.55 C1.2@65.4,55.9
NetC2_1: C2.1 R6.1 | length 1.4
  Bottom Layer w0.25: C2.1@65.4,57.3 R6.1@65.4,58.7
NetC204_A_1: C204_A.1 C209_A.1 C214_A.1 R200_A.2 R201_A.1 | length 5.8
  Top Layer w0.75: C214_A.1@63,61.6 63.1,61.5 C209_A.1@64.6,61.5 ; R200_A.2@64.6,58.7 C204_A.1@64.6,60.1 C209_A.1@64.6,61.5 ; R201_A.1@64.6,62.9 C209_A.1@64.6,61.5
NetC204_B_1: C204_B.1 C209_B.1 C214_B.1 R200_B.2 R201_B.1 | length 5.8
  Top Layer w0.75: C214_B.1@63,39.6 63.1,39.5 C209_B.1@64.6,39.5 ; R200_B.2@64.6,36.7 C204_B.1@64.6,38.1 C209_B.1@64.6,39.5 ; R201_B.1@64.6,40.9 C209_B.1@64.6,39.5
NetC204_C_1: C204_C.1 C209_C.1 C214_C.1 R200_C.2 R201_C.1 | length 5.8
  Top Layer w0.75: C214_C.1@63,17.6 63.1,17.5 C209_C.1@64.6,17.5 ; R200_C.2@64.6,14.7 C204_C.1@64.6,16.1 C209_C.1@64.6,17.5 ; R201_C.1@64.6,18.9 C209_C.1@64.6,17.5
NetC210_A_1: C210_A.1 R202_A.2 R203_A.1 | length 2.8
  Top Layer w0.75: R202_A.2@68.2,69.7 R203_A.1@71,69.7
NetC210_A_2: C210_A.2 U200_A.11 | length 2.5
  Top Layer w0.25: U200_A.11@68.907,65.925 68.957,65.975 68.957,66.793 69.535,67.371 69.535,68.035 C210_A.2@69.6,68.1
NetC210_B_1: C210_B.1 R202_B.2 R203_B.1 | length 2.8
  Top Layer w0.75: R202_B.2@68.2,47.7 R203_B.1@71,47.7
NetC210_B_2: C210_B.2 U200_B.11 | length 2.5
  Top Layer w0.25: U200_B.11@68.907,43.925 68.957,43.975 68.957,44.793 69.535,45.371 69.535,46.035 C210_B.2@69.6,46.1
NetC210_C_1: C210_C.1 R202_C.2 R203_C.1 | length 2.8
  Top Layer w0.75: R202_C.2@68.2,25.7 R203_C.1@71,25.7
NetC210_C_2: C210_C.2 U200_C.11 | length 2.5
  Top Layer w0.25: U200_C.11@68.907,21.925 68.957,21.975 68.957,22.793 69.535,23.371 69.535,24.035 C210_C.2@69.6,24.1
NetC211_A_2: C211_A.2 R206_A.2 | length 2.5
  Bottom Layer w1: C211_A.2@77.816,58.8 77.891,58.725 80.225,58.725 R206_A.2@80.3,58.65
NetC211_B_2: C211_B.2 R206_B.2 | length 2.5
  Bottom Layer w1: C211_B.2@77.816,36.8 77.891,36.725 80.225,36.725 R206_B.2@80.3,36.65
NetC211_C_2: C211_C.2 R206_C.2 | length 2.5
  Bottom Layer w1: C211_C.2@77.824,14.808 77.899,14.733 80.233,14.733 R206_C.2@80.308,14.658
NetC212_A_1: C212_A.1 R205_A.2 U200_A.13 | length 3.5
  Top Layer w0.25: R205_A.2@66.2,64.3 v4(67.2,64.3) 67.225,64.325 U200_A.13@68.682,64.325
  Bottom Layer w0.25: C212_A.1@66.2,64.3 v4(67.2,64.3)
NetC212_B_1: C212_B.1 R205_B.2 U200_B.13 | length 3.5
  Top Layer w0.25: R205_B.2@66.2,42.3 66.225,42.325 67.4,42.325 U200_B.13@68.682,42.325
  Bottom Layer w0.25: C212_B.1@66.2,42.3 66.225,42.325 v4(67.2,42.325)
NetC212_C_1: C212_C.1 R205_C.2 U200_C.13 | length 3.5
  Top Layer w0.25: R205_C.2@66.2,20.3 66.225,20.325 U200_C.13@68.682,20.325
  Bottom Layer w0.25: C212_C.1@66.2,20.3 66.225,20.325 v4(67.2,20.325)
NetC213_A_1: C213_A.1 R204_A.2 U200_A.12 | length 3.8
  Top Layer w0.25: R204_A.2@66.2,65.7 v4(67.2,65.7) 68.075,64.825 U200_A.12@68.682,64.825
  Bottom Layer w0.25: C213_A.1@66.2,65.7 v4(67.2,65.7)
NetC213_B_1: C213_B.1 R204_B.2 U200_B.12 | length 3.8
  Top Layer w0.25: R204_B.2@66.2,43.7 v4(67.2,43.7) 68.075,42.825 U200_B.12@68.682,42.825
  Bottom Layer w0.25: C213_B.1@66.2,43.7 v4(67.2,43.7)
NetC213_C_1: C213_C.1 R204_C.2 U200_C.12 | length 3.8
  Top Layer w0.25: R204_C.2@66.2,21.7 v4(67.2,21.7) 68.075,20.825 U200_C.12@68.682,20.825
  Bottom Layer w0.25: C213_C.1@66.2,21.7 v4(67.2,21.7)
NetC403_CSA_1: C403_CSA.1 C408_CSA.1 R402_CSA.1 U400_CSA.3 | length 8.3
  Top Layer w0.2: U400_CSA.3@71.15,57.725 71.525,57.725 72.1,58.3 73.725,58.3 74.5,57.525 C408_CSA.1@74.5,57.5
  Top Layer w0.25: C408_CSA.1@74.5,57.5 C403_CSA.1@74.5,55.9 75.5,55.9 75.9,56.3 R402_CSA.1@77.1,56.3
NetC403_CSA_2: C403_CSA.2 C409_CSA.1 R403_CSA.1 U400_CSA.2 | length 8.2
  Top Layer w0.25: U400_CSA.2@71.15,57.075 71.675,57.075 72.1,57.5 C409_CSA.1@72.9,57.5 C403_CSA.2@72.9,55.9 72.925,55.9 73.275,55.55 73.275,55.525 73.9,54.9 R403_CSA.1@77.1,54.9
NetC403_CSB_1: C403_CSB.1 C408_CSB.1 R402_CSB.1 U400_CSB.3 | length 8.3
  Top Layer w0.2: U400_CSB.3@71.15,35.725 71.525,35.725 72.1,36.3 73.725,36.3 74.5,35.525 C408_CSB.1@74.5,35.5
  Top Layer w0.25: C408_CSB.1@74.5,35.5 C403_CSB.1@74.5,33.9 75.5,33.9 75.9,34.3 R402_CSB.1@77.1,34.3
NetC403_CSB_2: C403_CSB.2 C409_CSB.1 R403_CSB.1 U400_CSB.2 | length 8.2
  Top Layer w0.25: U400_CSB.2@71.15,35.075 71.675,35.075 72.1,35.5 C409_CSB.1@72.9,35.5 C403_CSB.2@72.9,33.9 72.925,33.9 73.275,33.55 73.275,33.525 73.9,32.9 R403_CSB.1@77.1,32.9
NetC403_CSC_1: C403_CSC.1 C408_CSC.1 R402_CSC.1 U400_CSC.3 | length 8.3
  Top Layer w0.2: U400_CSC.3@71.15,13.725 71.525,13.725 72.1,14.3 73.725,14.3 74.5,13.525 C408_CSC.1@74.5,13.5
  Top Layer w0.25: C408_CSC.1@74.5,13.5 C403_CSC.1@74.5,11.9 75.5,11.9 75.9,12.3 R402_CSC.1@77.1,12.3
NetC403_CSC_2: C403_CSC.2 C409_CSC.1 R403_CSC.1 U400_CSC.2 | length 8.2
  Top Layer w0.25: U400_CSC.2@71.15,13.075 71.675,13.075 72.1,13.5 C409_CSC.1@72.9,13.5 C403_CSC.2@72.9,11.9 72.925,11.9 73.275,11.55 73.275,11.525 73.9,10.9 R403_CSC.1@77.1,10.9
NetC406_CSA_1: C406_CSA.1 R404_CSA.2 U400_CSA.7 | length 4.7
  Top Layer w0.25: C406_CSA.1@65.2,54.3 R404_CSA.2@65.2,55.9 65.329,56.029 65.929,56.029 66.975,57.075 U400_CSA.7@67.85,57.075
NetC406_CSB_1: C406_CSB.1 R404_CSB.2 U400_CSB.7 | length 4.7
  Top Layer w0.25: C406_CSB.1@65.2,32.3 R404_CSB.2@65.2,33.9 65.329,34.029 65.929,34.029 66.975,35.075 U400_CSB.7@67.85,35.075
NetC406_CSC_1: C406_CSC.1 R404_CSC.2 U400_CSC.7 | length 4.7
  Top Layer w0.25: C406_CSC.1@65.2,10.3 R404_CSC.2@65.2,11.9 65.329,12.029 65.929,12.029 66.975,13.075 U400_CSC.7@67.85,13.075
NetC407_CSA_1: C407_CSA.1 R405_CSA.2 U400_CSA.6 | length 6.5
  Top Layer w0.2: C407_CSA.1@63.6,54.3 63.6,54.325 63.975,54.7 64,54.7 64.4,55.1 64.4,56.5 64.8,56.9 64.8,56.925 65.175,57.3 R405_CSA.2@65.2,57.3
  Top Layer w0.25: R405_CSA.2@65.2,57.3 66.5,57.3 66.925,57.725 U400_CSA.6@67.85,57.725
NetC407_CSB_1: C407_CSB.1 R405_CSB.2 U400_CSB.6 | length 6.5
  Top Layer w0.2: C407_CSB.1@63.6,32.3 63.6,32.325 63.975,32.7 64,32.7 64.4,33.1 64.4,34.5 64.8,34.9 64.8,34.925 65.175,35.3 R405_CSB.2@65.2,35.3
  Top Layer w0.25: R405_CSB.2@65.2,35.3 66.5,35.3 66.925,35.725 U400_CSB.6@67.85,35.725
NetC407_CSC_1: C407_CSC.1 R405_CSC.2 U400_CSC.6 | length 6.5
  Top Layer w0.2: C407_CSC.1@63.6,10.3 63.6,10.325 63.975,10.7 64,10.7 64.4,11.1 64.4,12.5 64.8,12.9 64.8,12.925 65.175,13.3 R405_CSC.2@65.2,13.3
  Top Layer w0.25: R405_CSC.2@65.2,13.3 66.5,13.3 66.925,13.725 U400_CSC.6@67.85,13.725
NetC500_2: C500.2 C507.1 | length 2
  Top Layer w0.75: C507.1@16,52.016 C500.2@16,53.984
NetC504_1: C504.1 L500.1 Q500.2 U500.4 | length 31.7
  Top Layer w0.25: U500.4@26.475,66.15 26.475,63.525 28,62 Q500.2@39,62 ; U500.4@26.675,66.15 U500.4@26.85,65.975
  Top Layer w1: C504.1@26.7,54.45 29.833,57.583 34.992,57.583 39,61.591 Q500.2@39,62
NetC506_2: C506.2 U500.1 | length 1.9
  Top Layer w0.25: U500.1@23.725,68.05 23.925,68.05 24.1,68.225 24.1,68.425 24.3,68.625 C506.2@24.3,69.6
NetC508_1: C508.1 U501.7 | length 2.4
  Top Layer w0.25: U501.7@26.235,23.225 26.235,21.35 26.585,21 C508.1@26.6,21
NetC508_2: C508.2 L501.1 U501.8
NetC509_1: C509.1 C510.1 R504.1 R506.1 U501.3
NetC511_2: C511.2 C512.2 L501.2 R505.2 R507.2 | length 10.6
  Top Layer w0.25: R507.2@31.5,21 31.525,21 31.875,21.35 31.875,21.375 32.2,21.7 33.4,21.7 33.7,22 33.7,28.179 33.554,28.325 33.125,28.325 32.4,29.05 L501.2@32.4,29.2
NetC513_1: C513.1 U502.1 | length 9.2
  Top Layer w0.25: C513.1@38.5,25.2 38.85,24.85 38.85,24.45 39.4,23.9 41.1,23.9 41.3,24.1 41.3,28.2 41.65,28.55 U502.1@42.6,28.55
NetC513_2: C513.2 L502.1 U502.6
NetC514_1: C514.1 C516.1 L502.2 R512.2 R513.2 | length 6.7
  Top Layer w0.25: R513.2@46.2,26.8 46.2,26.825 46.55,27.175 46.875,27.175 47.1,27.4 47.1,31.722 46.772,32.05 46.55,32.05 C514.1@46.2,32.4
NetC515_1: C515.1 C517.1 R514.1 R515.2 U502.5
NetC600_1: C600.1 D600.2 J600.12 R608.1 | length 8.9
  Top Layer w0.25: J600.12@13.36,16.3 14.5,16.3 15,15.8 R608.1@16.7,15.8 17.075,16.132 17.079,16.132 17.925,16.872 C600.1@18.3,17.2
  Bottom Layer w0.25: J600.12@13.36,16.3 15.06,18 D600.2@15.9,18
NetC601_1: C601.1 D601.2 J600.10 R607.1 | length 8.6
  Top Layer w0.25: J600.10@13.36,18.84 15.06,18.84 15.3,18.6 R607.1@16.7,18.6 17.075,18.928 17.925,19.672 C601.1@18.3,20
  Bottom Layer w0.25: J600.10@13.36,18.84 14.476,18.84 15.461,19.825 15.725,19.825 D601.2@15.9,20
NetC602_1: C602.1 D602.2 J600.8 R606.1 | length 8.3
  Top Layer w0.25: J600.8@13.36,21.38 16.68,21.38 R606.1@16.7,21.4 17.075,21.728 17.925,22.472 C602.1@18.3,22.8
  Bottom Layer w0.25: J600.8@13.36,21.38 14.48,21.38 15.1,22 D602.2@15.9,22
NetC603_1: C603.1 D603.2 J600.6 R605.1 | length 8.2
  Top Layer w0.25: J600.6@13.36,23.92 14.82,23.92 15.1,24.2 R605.1@16.7,24.2 17.075,24.528 17.925,25.272 C603.1@18.3,25.6
  Bottom Layer w0.25: J600.6@13.36,23.92 15.82,23.92 D603.2@15.9,24
NetC604_1: C604.1 J600.20 R615.1 | length 5.3
  Top Layer w0.25: J600.20@13.36,6.14 16.46,6.14 R615.1@16.5,6.1 16.875,5.772 17.725,5.028 C604.1@18.1,4.7
NetD604_1: D604.1 R619.2 | length 2
  Top Layer w0.25: R619.2@51.1,6.5 51.154,6.446 D604.1@51.154,4.5
NetD605_1: D605.1 R620.2 | length 4.4
  Top Layer w0.25: R620.2@45.7,6.5 45.725,6.5 46.075,6.15 46.075,6.125 46.885,5.315 48.485,5.315 D605.1@49.3,4.5
NetJ600_1: J600.1 R603.1 | length 2.7
  Top Layer w0.75: R603.1@10.8,31.7 10.8,29 J600.1@10.82,29
NetJ600_2: J600.2 R604.2 | length 2.7
  Top Layer w0.75: J600.2@13.36,29 13.36,31.7 R604.2@13.4,31.7
NetJ600_3: J600.3
NetJ600_9: J600.9
NetJ600_11: J600.11 R617.1 | length 2.3
  Top Layer w0.25: R617.1@9,17.4 9.72,17.4 J600.11@10.82,16.3
NetJ600_13: J600.13 R618.1 R621.1 U600.2 | length 14.8
  Top Layer w0.25: R621.1@9,11.2 R618.1@9,12.7 9.76,12.7 J600.13@10.82,13.76 ; v1(15.1,8.7) 15.2,8.7 15.22,8.68 16.62,8.68 16.9,8.4 17.6,8.4 17.805,8.605 18.25,8.605 U600.2@18.325,8.68
  Int2 (PWR) w0.25: J600.13@10.82,13.76 12.1,12.48 12.1,10.4 12.6,9.9 13.9,9.9 v1(15.1,8.7)
NetJ600_14: J600.14 R613.1 | length 3
  Bottom Layer w0.25: J600.14@13.36,13.76 14.32,12.8 R613.1@16,12.8
NetJ600_15: J600.15
NetJ600_16: J600.16
NetJ600_18: J600.18
NetJ601_4: J601.4
NetJ601_6: J601.6
NetJ601_8: J601.8
NetJ601_10: J601.10
NetJ601_13: J601.13
NetJ601_15: J601.15 R614.2 | length 2.9
  Bottom Layer w0.25: R614.2@51.5,12.2 51.5,12.175 51.85,11.825 51.875,11.825 52.48,11.22 J601.15@54,11.22
NetJ601_16: J601.16
NetJ601_17: J601.17
NetJ601_18: J601.18
NetJ601_19: J601.19
NetJ601_20: J601.20 R612.2 | length 3.3
  Bottom Layer w0.25: R612.2@56.1,3 56.1,4.2 56.54,4.64 J601.20@56.54,6.14
NetNT600_1: NT600.1 NT601.1 NT602.1 R617.2 R618.2 | length 51
  Top Layer w0.25: R618.2@8.625,13.925 8.65,13.925 9,14.275 R618.2@9,14.3 ; NT600.1@9,19.238 9,19.1 8.2,18.3 8.2,16.6 8.625,16.175 8.65,16.175 9,15.825 R617.2@9,15.8 R618.2@9,14.3 ; NT602.1@50.6,10 19.5,10 19,10.5 15.9,10.5 13.9,12.5 12.8,12.5 12.446,12.854 NT601.1@12.1,12.854 12.1,14.4 11.5,15 10.2,15 9.8,14.6 9.3,14.6 R618.2@9,14.3
NetQ500_1: Q500.1 U500.5 | length 4.4
  Top Layer w0.25: U500.5@26.298,67.1 27.3,67.1 27.943,66.457 27.943,65.043 28.446,64.54 Q500.1@28.8,64.54
NetR201_A_2: R201_A.2 U200_A.14 | length 2.9
  Top Layer w0.25: R201_A.2@66.2,62.9 66.229,62.929 67.129,62.929 68.025,63.825 U200_A.14@68.682,63.825
NetR201_B_2: R201_B.2 U200_B.14 | length 2.9
  Top Layer w0.25: R201_B.2@66.2,40.9 66.229,40.929 67.129,40.929 68.025,41.825 U200_B.14@68.682,41.825
NetR201_C_2: R201_C.2 U200_C.14 | length 2.9
  Top Layer w0.25: R201_C.2@66.2,18.9 66.229,18.929 67.129,18.929 68.025,19.825 U200_C.14@68.682,19.825
NetR203_A_2: R203_A.2 U200_A.10 | length 3.2
  Top Layer w0.25: U200_A.10@69.457,66.1 69.457,66.657 69.7,66.9 70.7,66.9 71,67.2 R203_A.2@71,68.1
NetR203_B_2: R203_B.2 U200_B.10 | length 3.2
  Top Layer w0.25: U200_B.10@69.457,44.1 69.457,44.657 69.7,44.9 70.7,44.9 71,45.2 R203_B.2@71,46.1
NetR203_C_2: R203_C.2 U200_C.10 | length 3.2
  Top Layer w0.25: U200_C.10@69.457,22.1 69.457,22.657 69.7,22.9 70.7,22.9 71,23.2 R203_C.2@71,24.1
NetR503_1: R503.1 TP500.1 U500.3 | length 5.4
  Top Layer w0.25: U500.3@24.1,65.975 23.925,66.15 U500.3@23.725,66.15 23.8,66.075 R503.1@23.8,64.6 23.8,62.201 TP500.1@24.5,61.5
NetR506_2: R506.2 R509.1 U501.2 | length 10
  Top Layer w0.25: v1(20.4,31.8) R506.2@20.4,30.9 20.5,30.8 R509.1@20.5,29.3
  Bottom Layer w0.25: v1(20.4,31.8) 21.935,30.265 23.845,30.265 v1(26.235,27.875)
NetR507_1: R507.1 R511.2 U501.5 | length 13.7
  Top Layer w0.25: U501.5@23.695,23.225 23.695,22.925 23.57,22.8 R511.2@21.9,22.8 21.9,22 21.4,21.5 21.4,20.6 22,20 28.9,20 29.525,20.625 29.525,20.65 29.875,21 R507.1@29.9,21
NetR508_2: R508.2 U501.6 | length 2.3
  Top Layer w0.25: R508.2@24.9,21 24.965,21.065 U501.6@24.965,23.225
NetR510_2: R510.2 U501.4 | length 2
  Top Layer w0.25: R510.2@21.9,29.3 23.57,29.3 23.695,29.175 U501.4@23.695,28.975
NetR513_1: R513.1 R516.2 U502.3 | length 8.3
  Top Layer w0.25: R513.1@46.2,28.4 v1(46.2,29.8) R516.2@46.2,31
  Top Layer w0.5: v1(41.7,30.45) U502.3@42.6,30.45
  Bottom Layer w0.25: v1(41.7,30.45) 45.55,30.45 v1(46.2,29.8)
NetR615_2: R615.2 R616.1 RT600.2 | length 64.1
  Top Layer w0.25: R615.2@18.1,6.1 R616.1@19.6,6.1 v1(19.6,4.8) ; RT600.2@69.64,16.5 v1(70.4,16.5)
  Int2 (PWR) w0.25: v1(19.6,4.8) 20.6,4.8 23.1,2.3 57.3,2.3 61,6 61,8.2 63.4,10.6 67.1,10.6 68.4,11.9 68.4,14.5 v1(70.4,16.5)
NetU200_A_1: U200_A.1
NetU200_A_2: U200_A.2
NetU200_A_3: U200_A.3
NetU200_A_4: U200_A.4
NetU200_A_8: U200_A.8
NetU200_A_9: U200_A.9
NetU200_A_16: U200_A.16
NetU200_B_1: U200_B.1
NetU200_B_2: U200_B.2
NetU200_B_3: U200_B.3
NetU200_B_4: U200_B.4
NetU200_B_8: U200_B.8
NetU200_B_9: U200_B.9
NetU200_B_16: U200_B.16
NetU200_C_1: U200_C.1
NetU200_C_2: U200_C.2
NetU200_C_3: U200_C.3
NetU200_C_4: U200_C.4
NetU200_C_8: U200_C.8
NetU200_C_9: U200_C.9
NetU200_C_16: U200_C.16
NetU600_1: U600.1
P3V3: C401_CSA.1 C401_CSB.1 C401_CSC.1 C402_CSA.1 C402_CSB.1 C402_CSC.1 C605.1 D600.1 D601.1 D602.1 D603.1 D604.2 R5.1 R512.1 R603.2 R612.1 U400_CSA.8 U400_CSB.8 U400_CSC.8 U600.5 | length 190.2
  Top Layer w0.25: U600.5@16.075,8.03 16.15,7.955 16.375,7.955 16.652,7.678 17.178,7.678 v1(17.2,7.7)
  Top Layer w0.5: D604.2@51.154,2.9 51.254,3 v1(53.6,3)
  Top Layer w0.75: v1(8.4,33.3) v1(9.2,33.3) v1(10,33.3) R603.2@10.8,33.3 ; v1(19.7,23.9) v1(20.4,23.2) v1(20.4,22.2) 20.4,20.1 21.4,19.1 34.8,19.1 v2(38.5,22.8) R512.1@44.3,22.8
  Int1 (GND) w0.5: v1(65.6,44.9) 65.562,44.862 65.562,44.644 65.4,44.482 65.4,36.9 66.8,35.5 v1(66.8,33.4)
  Int2 (PWR) w0.5: v1(20.4,22.2) 19,20.8 19,9.5 v1(17.2,7.7) 17.2,6.9 17.761,6.339 20.261,6.339 23.6,3 v1(53.6,3) 57.1,3 60.4,6.3 60.4,8.5 63.3,11.4 v1(66.8,11.4) 66.8,12.5 67.7,13.4 67.7,15 68.1,15.4 68.1,18 65.7,20.4 65.7,21.3 66.5,22.1 66.5,25.8 65.7,26.6 65.7,29.1 66.8,30.2 v1(66.8,33.4)
  Int2 (PWR) w0.75: v1(8.4,33.3) v1(9.2,33.3) v1(10,33.3) 12.6,30.7 16.5,30.7 19.7,27.5 v1(19.7,23.9) v1(20.4,23.2) v1(20.4,22.2)
  Bottom Layer w0.25: R5.1@65.625,54.725 65.629,54.729 66.129,54.729
  Bottom Layer w0.5: D600.1@18.1,18 D601.1@18.1,20 D602.1@18.1,22 D603.1@18.1,24 ; D603.1@18.15,23.95 D603.1@18.1,24 ; v1(19.7,23.9) 19.646,23.9 19.546,24 D603.1@18.1,24 ; v1(53.6,3) R612.1@54.5,3 ; v1(65.6,44.9) 65.6,46.832 67.7,48.932 67.7,54.5 v1(66.8,55.4) 66.129,54.729 66.125,54.725 R5.1@65.625,54.725
  Bottom Layer w0.75: v1(17.2,7.7) C605.1@18.3,7.7 ; v1(19.7,23.9) v1(20.4,23.2) v1(20.4,22.2)
P5V: D605.2 R200_A.1 R200_B.1 R200_C.1 R505.1 R514.2 R604.1 R616.2 | length 166.9
  Top Layer w0.5: v1(47.9,4.1) 47.9,3.609 48.584,2.925 D605.2@49.275,2.925
  Top Layer w0.75: R604.1@13.4,33.3 v5(14.8,33.3) v1(14.8,32.1) ; R616.2@21.2,6.1 v1(22,6.1) ; D605.2@49.275,2.925 D605.2@49.3,2.9 ; R200_C.1@66.2,14.7 66.213,14.687 v1(66.825,14.687) ; R200_B.1@66.2,36.7 66.213,36.687 v1(66.825,36.687) ; R200_A.1@66.2,58.7 66.213,58.687 v1(66.825,58.687)
  Int1 (GND) w0.75: v1(66.7,44.9) 66.7,44.6 66.275,44.175 66.275,37.237 v1(66.825,36.687)
  Int2 (PWR) w0.75: 15.6,32.8 15.6,32.7 16.2,32.1 ; 15.6,32.9 v1(14.8,32.1) ; v1(66.825,36.687) 64,33.862 64,26.9 65.6,25.3 65.6,22.4 64.8,21.6 64.8,16.712 v1(66.825,14.687) 66.825,13.925 65.3,12.4 62.9,12.4 59.4,8.9 59.4,6.7 56.8,4.1 v1(47.9,4.1) 24,4.1 21.1,7 21.1,21.4 21.7,22 21.7,24.063 20.9,24.863 20.9,29.6 ; v1(14.8,32.1) 16.2,32.1 ; v1(14.8,32.1) v5(14.8,33.3) 15.7,33.3 16.9,32.1 ; 16.2,32.1 16.9,32.1 ; 16.9,32.1 19.4,29.6 20.9,29.6 ; 20.9,29.6 31.7,29.6 34,31.9 v1(34,33.8) ; v1(34,33.8) v1(34,35) v1(35.2,35) v1(35.8,34.4) v1(34.6,34.4) v1(34,33.8)
  Bottom Layer w0.75: v1(66.7,44.9) 66.7,46.7 68.6,48.6 68.6,55 66.825,56.775 v1(66.825,58.687)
